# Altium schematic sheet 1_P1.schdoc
size 309 x 223 mm; Symbol: Sheet-Symbol_A4; Device: Sheet-Symbol_A4; Company: 嘉立创EDA; Version: V1.0; Page Size: A4; @Project Name: 温度传感器; @Page Count: 1; @Update Date: 2024-11-23; @Create Date: 2024-11-23; @Schematic Name: Schematic1; @Page No: 1; @Page Name: P1; @Board Name: Board1; @Create Time: 20:42:42; @Update Time: 20:53:47
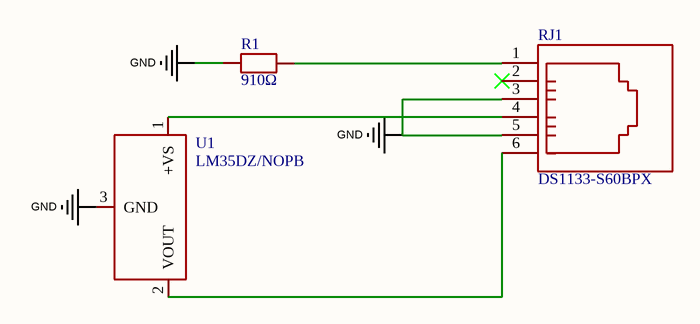
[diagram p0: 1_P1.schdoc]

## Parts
R1  910Ω  [R0805]  (value not drawn)
RJ1  DS1133-S60BPX  [RJ11-TH_DS1133-S60BPX]  (value not drawn)
U1  LM35DZ/NOPB  [TO-92-3_L4.9-W3.7-P1.27-L]  (value not drawn)

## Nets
GND: R1.1 RJ1.3 RJ1.5 U1.3(GND)
NetR1_2: R1.2 RJ1.1
NetRJ1_4: RJ1.4 U1.1(+VS)
NetRJ1_6: RJ1.6 U1.2(VOUT)

Not connected (* = marked no-connect by the designer): RJ1 2*

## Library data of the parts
R1 = FRC0805F9100TS: 电阻类型:厚膜电阻;阻值:910Ω;精度:±1%;功率:125mW;最大工作电压:150V;温度系数:±100ppm/℃;; Manufacturer: FOJAN(富捷); Add into BOM: yes; Tolerance: ±1%; Power(Watts): 125mW; Overload Voltage (Max): 150V
RJ1 = DS1133-S60BPX: 连接器类型:RJ12插座;端口数量:1;屏蔽:-;LED:-;等级:-;; Manufacturer: CONNFLY; Add into BOM: yes; Connector Type: RJ12插座; Number of Ports: 1
U1 = LM35DZ/NOPB: 精度:±1.5℃;; Manufacturer: TI(德州仪器); Symbol: LM35DZ; Add into BOM: yes; Resolution: ±1.5℃; Supply Voltage: 4V~30V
